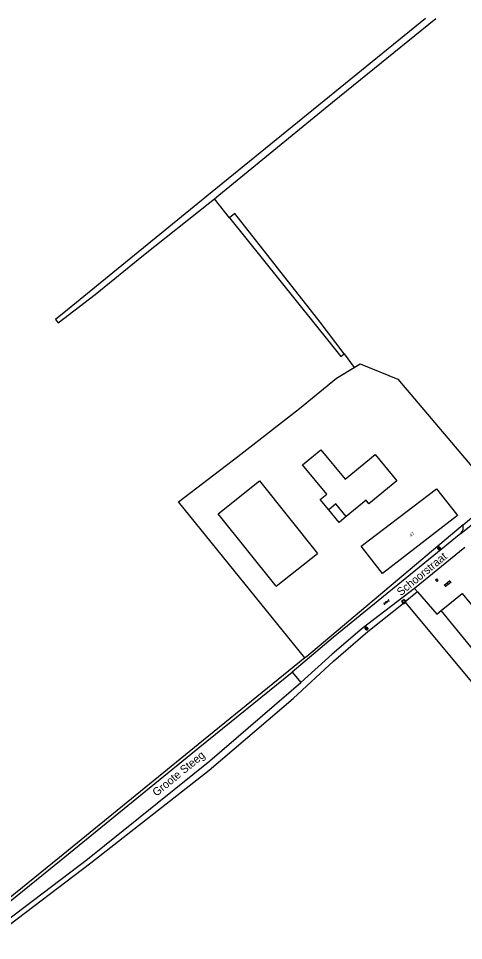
# Model space of a CAD drawing. Extents: x 136000 to 141014, y 402000 to 403500.
# Drawn here: x 136361.5 to 136500.5, y 403212 to 403500 of the extents above; entities that cross this region are included whole.
import ezdxf

# ---------------------------------------------------------------- set-up
doc = ezdxf.new("R2010")
doc.units = 0
for name, color, linetype in [('gg-afsc-draadraster', 7, 'Continuous'), ('gg-afsc-lijn draadraster', 7, 'Continuous'), ('gg-anno-huisnummerreeks BGT', 7, 'Continuous'), ('gg-anno-openbare ruimte label', 7, 'Continuous'), ('gg-bbg-bijgebouw', 7, 'Continuous'), ('gg-bbg-gedigitaliseerde bijgebouw', 7, 'Continuous'), ('gg-bbg-hoofdgebouw', 7, 'Continuous'), ('gg-bbg-luifel en loopbrug', 7, 'Continuous'), ('gg-knt-bronhoudergrens', 7, 'Continuous'), ('gg-knt-onverhard', 7, 'Continuous'), ('gg-knt-verharding', 7, 'Continuous'), ('gg-kntw-bovenkant insteek waterloop', 7, 'Continuous'), ('gt-grn-groengrens', 7, 'Continuous'), ('gt-symb-gesloten verharding', 7, 'Continuous'), ('gt-symb-klinker verharding', 7, 'Continuous'), ('gt-symb-kolk center center', 7, 'Continuous'), ('gt-symb-lichtmast', 7, 'Continuous'), ('gt-symb-rioolschacht', 7, 'Continuous')]:
    doc.layers.add(name, color=color, linetype=linetype)

# ---------------------------------------------------------------- blocks, each defined once
blk = doc.blocks.new('gt0-LMAST')
at = {"layer": 'gt-symb-lichtmast'}
for p, q in [((-0.18, 0.17), (-0.45, 0.44)), ((0, 0.25), (0, 0.62)), ((0.17, 0.17), (0.44, 0.44)), ((-0.25, 0), (-0.63, 0)), ((-0.18, -0.18), (-0.45, -0.45)), ((0, -0.25), (0, -0.63)), ((0.44, -0.45), (0.17, -0.18)), ((0.25, 0), (0.62, 0))]:
    blk.add_line(p, q, dxfattribs=at)
blk.add_circle((0, 0), 0.25, dxfattribs=at)
blk = doc.blocks.new('gt0-GESVH1')
at = {"layer": 'gt-symb-gesloten verharding'}
for p, q in [((-0.99, -0.26), (0.01, 0.24)), ((0.01, -0.26), (-0.99, 0.24)), ((0.01, 0.24), (1.01, -0.26)), ((1.01, 0.24), (0.01, -0.26))]:
    blk.add_line(p, q, dxfattribs=at)
blk = doc.blocks.new('gt0-RS')
at = {"layer": 'gt-symb-rioolschacht'}
blk.add_lwpolyline([(-0.5, -0.5), (0.5, -0.5), (0.5, 0.5), (-0.5, 0.5)], close=True, dxfattribs=at)
blk.add_circle((0, 0), 0.375, dxfattribs=at)
blk = doc.blocks.new('gt0-KOLKCC')
at = {"layer": 'gt-symb-kolk center center'}
blk.add_lwpolyline([(-0.37, 0.2), (0.38, 0.2), (0.38, -0.2), (-0.37, -0.2)], close=True, dxfattribs=at)
blk = doc.blocks.new('gt0-KL1')
at = {"layer": 'gt-symb-klinker verharding'}
for p, q in [((-1.15, 0.3), (1.15, 0.3)), ((-1, -0.3), (-1, 0.3)), ((-0.5, 0.3), (-0.5, 0.45)), ((0, -0.3), (0, 0.3)), ((0.5, 0.3), (0.5, 0.45)), ((1, -0.3), (1, 0.3)), ((-1.15, -0.3), (1.15, -0.3)), ((-0.5, -0.45), (-0.5, -0.3)), ((0.5, -0.45), (0.5, -0.3))]:
    blk.add_line(p, q, dxfattribs=at)

msp = doc.modelspace()

# ---------------------------------------------------------------- linework, layer by layer
at = {"layer": 'gg-afsc-draadraster'}
msp.add_line((136480.04, 403387.34), (136510.83, 403350.89), dxfattribs=at)
at = {"layer": 'gg-afsc-lijn draadraster'}
msp.add_line((136480.04, 403387.34), (136510.83, 403350.89), dxfattribs=at)
at = {"layer": 'gg-bbg-bijgebouw'}
msp.add_line((136442.08, 403322.61), (136454.96, 403332.91), dxfattribs=at)
for points in [[(136479.72, 403355.53), (136471.01, 403348.38), (136470.09, 403349.5)], [(136493.6, 403315.05), (136500.1, 403320.41), (136502.47, 403317.5)], [(136502.47, 403317.5), (136510.32, 403307.88), (136503.78, 403302.55), (136493.6, 403315.05)]]:
    msp.add_lwpolyline(points, dxfattribs=at)
at = {"layer": 'gg-bbg-gedigitaliseerde bijgebouw'}
msp.add_line((136470.09, 403349.5), (136463.93, 403344.42), dxfattribs=at)
for points in [[(136458.45, 403346.52), (136455.82, 403349.72), (136457.85, 403351.39), (136450.28, 403360.6), (136455.97, 403365.27), (136463.53, 403356.06), (136472.94, 403363.79), (136479.72, 403355.53)], [(136442.08, 403322.61), (136423.96, 403345.28), (136436.83, 403355.57), (136454.96, 403332.91)], [(136463.93, 403344.42), (136460.69, 403348.36), (136458.45, 403346.52)]]:
    msp.add_lwpolyline(points, dxfattribs=at)
at = {"layer": 'gg-bbg-hoofdgebouw'}
for points in [[(136498.7, 403344.78), (136475.22, 403326.64), (136468.58, 403335.12), (136492.09, 403353.1)], [(136492.09, 403353.1), (136498.3, 403345.13), (136498.39, 403345.2), (136498.7, 403344.78)]]:
    msp.add_lwpolyline(points, dxfattribs=at)
at = {"layer": 'gg-bbg-luifel en loopbrug'}
msp.add_lwpolyline([(136463.93, 403344.42), (136461.7, 403342.59), (136458.45, 403346.52)], dxfattribs=at)
at = {"layer": 'gg-knt-bronhoudergrens'}
for p, q in [((136427.48, 403437.76), (136422.73, 403443.68)), ((136463.22, 403395.19), (136466.36, 403390.98)), ((136500.4, 403341.78), (136507.13, 403347.44)), ((136500.4, 403341.78), (136451.46, 403300.61)), ((136486.12, 403320.92), (136482.29, 403317.81)), ((136559.61, 403224.56), (136482.29, 403317.81)), ((136451.46, 403300.61), (136451.02, 403300.26))]:
    msp.add_line(p, q, dxfattribs=at)
for points in [[(136451.02, 403300.26), (136411.5, 403348.97), (136430.05, 403363.14), (136449.29, 403378.2), (136460.82, 403387.59), (136466.36, 403390.98)], [(136466.36, 403390.98), (136468.31, 403392.12), (136480.04, 403387.34)], [(136355.91, 403214.79), (136384.1, 403236.23), (136421.13, 403265.23), (136447.35, 403287.59), (136459.98, 403299.25), (136470.62, 403308.45), (136482.29, 403317.81)], [(136451.02, 403300.26), (136417.69, 403273.18), (136374.33, 403237.86), (136321.97, 403195.49), (136273.92, 403155.39), (136227, 403118.07), (136197.85, 403094.49), (136176.99, 403077.43), (136165.93, 403067.82)]]:
    msp.add_lwpolyline(points, dxfattribs=at)
at = {"layer": 'gg-knt-onverhard'}
for points in [[(136166.78, 403066.78), (136177.57, 403076.76), (136198.41, 403093.82), (136227.55, 403117.39), (136274.48, 403154.71), (136322.52, 403194.81), (136374.89, 403237.18), (136418.24, 403272.5), (136447.05, 403295.84)], [(136354.88, 403216.05), (136383.07, 403237.36), (136421.3, 403268.07), (136449.77, 403292.52)]]:
    msp.add_lwpolyline(points, dxfattribs=at)
at = {"layer": 'gg-knt-verharding'}
for p, q in [((136499.74, 403339.15), (136509.96, 403347.47)), ((136500.9, 403334.75), (136485.23, 403321.95)), ((136485.23, 403321.95), (136486.12, 403320.92)), ((136447.05, 403295.84), (136449.77, 403292.52))]:
    msp.add_line(p, q, dxfattribs=at)
for points in [[(136499.74, 403339.15), (136459.79, 403306.62), (136447.05, 403295.84)], [(136485.23, 403321.95), (136468.9, 403309.46), (136459.52, 403301.41), (136449.77, 403292.52)], [(136486.12, 403320.92), (136492.16, 403313.93), (136493.6, 403315.05)]]:
    msp.add_lwpolyline(points, dxfattribs=at)
at = {"layer": 'gg-kntw-bovenkant insteek waterloop'}
for points in [[(136488.64, 403500), (136420.35, 403444.52), (136389.83, 403419.6), (136376.91, 403409.01), (136373.08, 403405.97), (136373.95, 403404.94), (136385.51, 403413.8), (136400.55, 403426.1), (136421.31, 403442.55), (136422.73, 403443.68)], [(136422.73, 403443.68), (136424.08, 403444.75), (136459.6, 403473.84), (136491.87, 403500)], [(136463.22, 403395.19), (136455.81, 403405.1), (136429.17, 403439.09), (136427.48, 403437.76)], [(136427.48, 403437.76), (136458.91, 403398.53), (136462.21, 403394.45), (136463.22, 403395.19)]]:
    msp.add_lwpolyline(points, dxfattribs=at)
at = {"layer": 'gt-grn-groengrens'}
msp.add_arc((136497.55, 403341.09), 2.93, 318.5079, 13.5839, dxfattribs=at)

# ---------------------------------------------------------------- block references
at = {"layer": 'gt-symb-gesloten verharding', "rotation": 40.01095772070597}
msp.add_blockref('gt0-GESVH1', (136476.45, 403317.67), dxfattribs=at)
at = {"layer": 'gt-symb-klinker verharding', "rotation": 38.62400399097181}
msp.add_blockref('gt0-KL1', (136495.56, 403323.5), dxfattribs=at)
at = {"layer": 'gt-symb-kolk center center', "rotation": 132.16188122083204}
msp.add_blockref('gt0-KOLKCC', (136492.16, 403324.49), dxfattribs=at)
at = {"layer": 'gt-symb-lichtmast'}
for p in [(136492.92, 403334.46), (136470.25, 403309.45)]:
    msp.add_blockref('gt0-LMAST', p, dxfattribs=at)
at = {"layer": 'gt-symb-rioolschacht', "rotation": 39.196688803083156}
msp.add_blockref('gt0-RS', (136481.89, 403317.84), dxfattribs=at)

# ---------------------------------------------------------------- texts
at = {"layer": 'gg-anno-huisnummerreeks BGT'}
msp.add_text('47', height=1, rotation=37.7, dxfattribs=at).set_placement((136484.15, 403337.96))
at = {"layer": 'gg-anno-openbare ruimte label'}
for s, rotation, p in [('Schoorstraat', 39.4, (136480.96, 403319.48)), ('Groote Steeg', 39.3, (136404.64, 403256.85))]:
    msp.add_text(s, height=2.5, rotation=rotation, dxfattribs=at).set_placement(p)

doc.saveas('drawing.dxf')
